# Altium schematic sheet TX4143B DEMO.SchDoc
size A
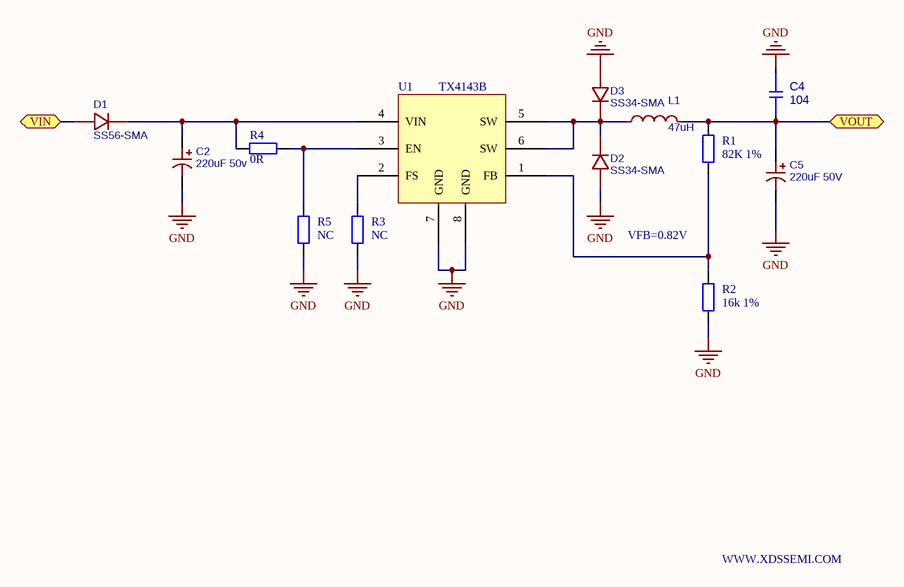
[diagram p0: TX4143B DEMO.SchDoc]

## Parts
C2  220uF 50v  [CAP-TH_BD10.0-P5.00-D0.6-FD]
C4  104  [0402]
C5  220uF 50V  [CAP-TH_BD10.0-P5.00-D0.6-FD]
D1  SS56-SMA  [SMB_L4.4-W3.6-LS5.3-RD]
D2  SS34-SMA  [SMB_L4.4-W3.6-LS5.3-RD]
D3  SS34-SMA  [SMB_L4.4-W3.6-LS5.3-RD]
L1  47uH  [IND-SMD_L13.2-W12.8_YXMAC12XX]
R1  82K 1%  [0805_R]
R2  16k 1%  [0805_R]
R3  NC  [0805_R]
R4  0R  [0805_R]
R5  NC  [0805_R]
U1  TX4143B  [SOP-8(150MIL)]

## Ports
VIN, VOUT

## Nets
GND: C2.2 C4.1 C5.2 D2.2(A) D3.2(A) R2.1 R3.1 R5.1 U1.7(GND) U1.8(GND)
VIN: D1.2(A) ; port VIN
VOUT: C4.2 C5.1 L1.2 R1.2 ; port VOUT
NetC2_1: C2.1 D1.1(C) R4.1 U1.4(VIN)
NetD2_1: D2.1(C) D3.1(C) L1.1 U1.5(SW) U1.6(SW)
NetR1_1: R1.1 R2.2 U1.1(FB)
NetR3_2: R3.2 U1.2(FS)
NetR4_2: R4.2 R5.2 U1.3(EN)

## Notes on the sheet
- VFB=0.82V
- WWW.XDSSEMI.COM

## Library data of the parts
C2 C5 = 220uF: BOM_Manufacturer Part: EEUEB1H221; nameAlias: Capacitance; Contributor: LCSC
C4 = 电容(无极性)
D1-D3 = SS34-SMB: Contributor: LCSC
L1 = 680nH: BOM_Manufacturer: YUXIN TECH; BOM_Manufacturer Part: YXMAC1250-R68M-ITF; nameAlias: Inductance; Contributor: LCSC
R1-R5 = 0805 1Ω (1R00) 1%: 贴片电阻
U1 = Component_1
